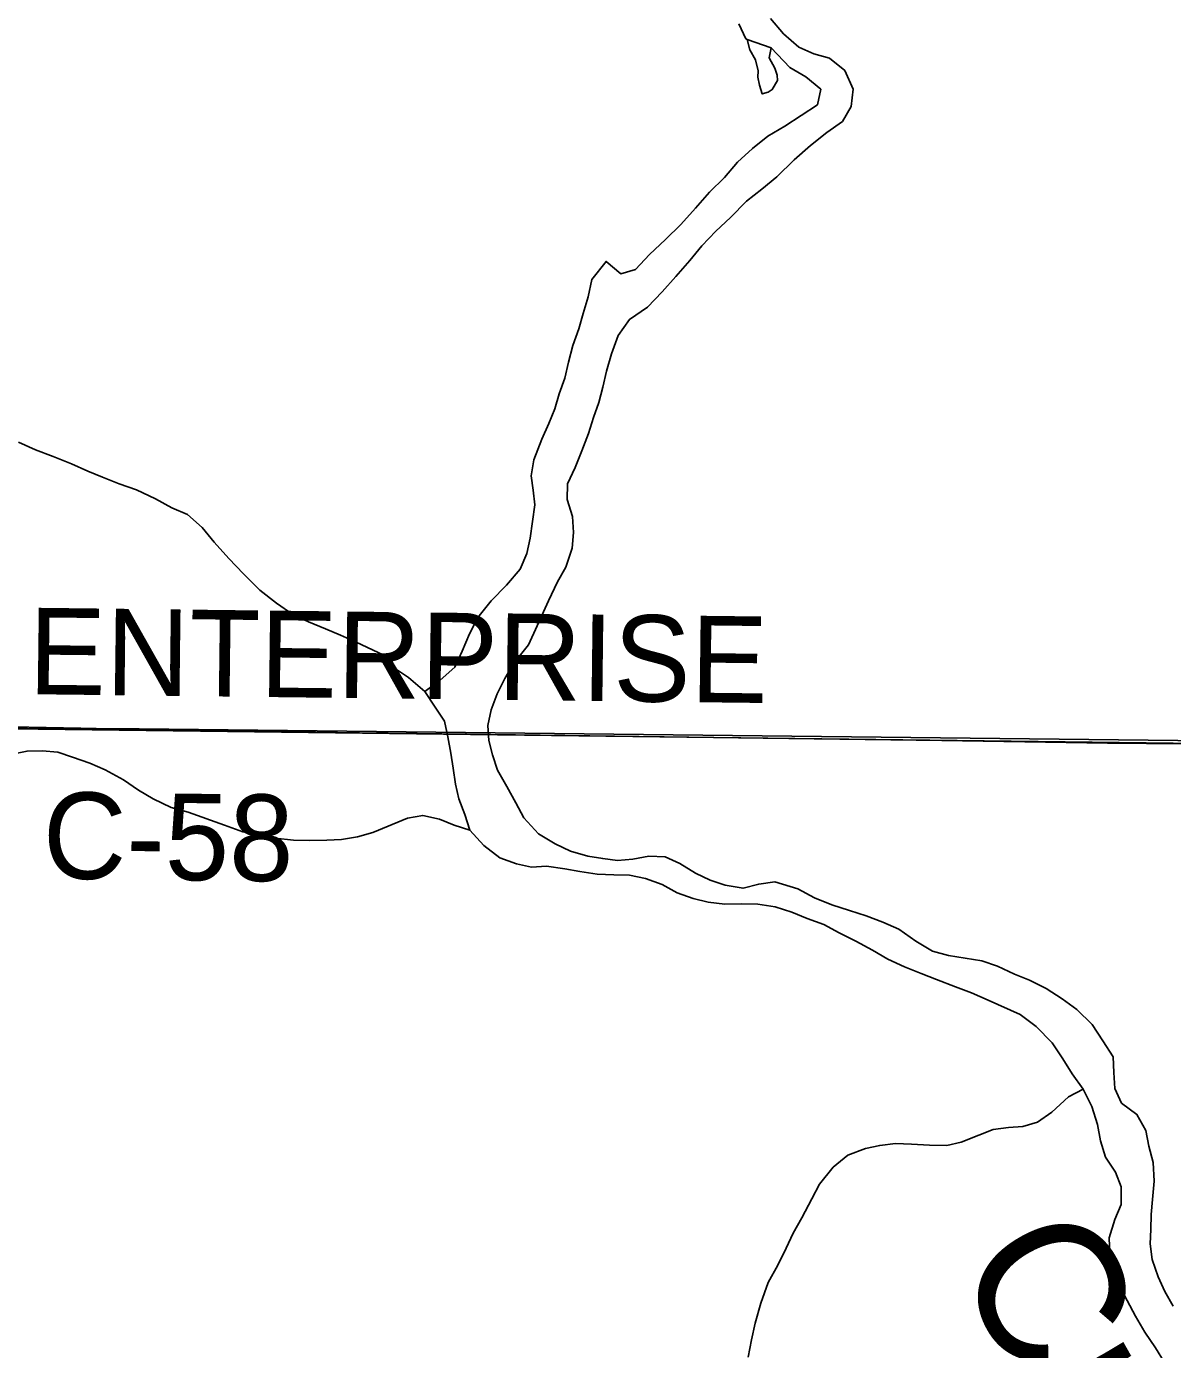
# Model space of a CAD drawing. Extents: x 0 to 34, y 0 to 22.
# Drawn here: x 7.507 to 8.26, y 17.907 to 18.776 of the extents above; entities that cross this region are included whole.
import ezdxf

# ---------------------------------------------------------------- set-up
doc = ezdxf.new("R2010")
doc.units = 0
for name, color, linetype in [('GM_X_Corporation', 7, 'Continuous'), ('GM_X_County_Road', 7, 'Continuous'), ('GM_X_County_Road_Text', 7, 'Continuous'), ('GM_X_Major_River', 7, 'Continuous'), ('GM_X_Major_River_Text', 7, 'Continuous'), ('GM_X_Minor_River', 7, 'Continuous')]:
    doc.layers.add(name, color=color, linetype=linetype)

msp = doc.modelspace()

# ---------------------------------------------------------------- linework, layer by layer
at = {"layer": 'GM_X_Corporation'}
for points in [[(8.49605, 19.31157), (8.49105, 18.30258), (7.47882, 18.31519), (7.49347, 19.32059)], [(8.49105, 18.30258), (8.48901, 17.21889), (7.47417, 17.23266), (7.47882, 18.31519)]]:
    msp.add_lwpolyline(points, close=True, dxfattribs=at)
for points in [[(8.49711, 18.30455), (7.58097, 18.31487), (7.55261, 18.31519), (7.54255, 18.31539), (7.37173, 18.31874)], [(7.37173, 18.31874), (7.54255, 18.31539), (7.55261, 18.31519), (7.58097, 18.31487), (8.49711, 18.30455)]]:
    msp.add_lwpolyline(points, dxfattribs=at)
at = {"layer": 'GM_X_County_Road'}
for points in [[(7.48288, 18.31538), (7.58147, 18.31452), (7.72562, 18.3124), (7.76351, 18.31188)], [(7.76351, 18.31188), (7.84429, 18.31078), (7.99087, 18.3088), (8.10832, 18.30725), (8.21705, 18.3055), (8.37111, 18.30423), (8.45811, 18.30343), (8.49736, 18.30357)]]:
    msp.add_lwpolyline(points, dxfattribs=at)
at = {"layer": 'GM_X_Major_River'}
msp.add_line((7.99614, 18.76228), (7.98031, 18.76789), dxfattribs=at)
for points in [[(7.81, 18.31713), (7.81208, 18.32733), (7.81607, 18.33787), (7.82119, 18.34802), (7.82707, 18.35815), (7.83677, 18.3701), (7.84231, 18.38251), (7.84983, 18.39906), (7.85575, 18.41146), (7.86124, 18.42122), (7.86526, 18.43366), (7.86621, 18.44388), (7.86564, 18.4545), (7.86205, 18.46557), (7.86224, 18.4758), (7.86738, 18.4867), (7.87175, 18.49762), (7.87613, 18.50891), (7.87936, 18.51947), (7.88296, 18.52927), (7.88542, 18.53946), (7.88789, 18.55003), (7.89114, 18.56135), (7.89553, 18.5734), (7.90293, 18.58388), (7.91484, 18.592), (7.92451, 18.60206), (7.93343, 18.61213), (7.94273, 18.62258), (7.95049, 18.6323), (7.95978, 18.64198), (7.96943, 18.65091), (7.97987, 18.66171), (7.98988, 18.66949), (7.99989, 18.67765), (8.0111, 18.68882), (8.02189, 18.6981), (8.03268, 18.70662), (8.04306, 18.71401), (8.04855, 18.72377), (8.0499, 18.73512), (8.04443, 18.74736), (8.03434, 18.75551), (8.02414, 18.75835), (8.01436, 18.76271), (8.00428, 18.77162), (7.99574, 18.78163)], [(7.97481, 18.77823), (7.97956, 18.76828), (7.98031, 18.76789)], [(7.98031, 18.76789), (7.98208, 18.76103), (7.98575, 18.75451), (7.98752, 18.74727), (7.98744, 18.7431), (7.98848, 18.73778), (7.99027, 18.73206), (7.99408, 18.73312), (7.99677, 18.73497), (8.0003, 18.74097), (7.99998, 18.74439)], [(7.99614, 18.76228), (8.00843, 18.74954), (8.01893, 18.74328), (8.02865, 18.73514), (8.02657, 18.72494), (8.00506, 18.71092), (7.99393, 18.7043), (7.98392, 18.69615), (7.97389, 18.68723), (7.96536, 18.67715), (7.95569, 18.66747), (7.94639, 18.65702), (7.93671, 18.6462), (7.92667, 18.63653), (7.91624, 18.62648), (7.90695, 18.6168), (7.89742, 18.61394), (7.8877, 18.62208), (7.87837, 18.61012), (7.87589, 18.59879), (7.87265, 18.58785), (7.86981, 18.57767), (7.86581, 18.56674), (7.86296, 18.5558), (7.86048, 18.54523), (7.85688, 18.53506), (7.85405, 18.52525), (7.85007, 18.51546), (7.84533, 18.50531), (7.84015, 18.49176), (7.83844, 18.48117), (7.83978, 18.47167), (7.84074, 18.46217), (7.8394, 18.4512), (7.83768, 18.44023), (7.8356, 18.43003), (7.83124, 18.41988), (7.82232, 18.40942), (7.81226, 18.39899), (7.80334, 18.38816), (7.79782, 18.37727), (7.79306, 18.36598), (7.78832, 18.35545), (7.77867, 18.34691), (7.76867, 18.33951), (7.77495, 18.32991), (7.78159, 18.31993), (7.78368, 18.30965), (7.78576, 18.299), (7.7871, 18.28912), (7.7888, 18.27847), (7.7909, 18.26895), (7.79488, 18.25864), (7.79811, 18.24834), (7.80741, 18.23831), (7.81788, 18.23015), (7.82881, 18.22616), (7.83864, 18.22408), (7.84851, 18.22466), (7.86062, 18.22292), (7.87046, 18.22122), (7.88181, 18.21949), (7.8928, 18.21891), (7.90304, 18.21872), (7.91363, 18.21663), (7.92456, 18.21264), (7.93432, 18.20715), (7.94488, 18.20354), (7.9547, 18.20108), (7.96568, 18.19974), (7.9763, 18.19992), (7.9873, 18.19972), (7.99865, 18.198), (8.00959, 18.19438), (8.01976, 18.1904), (8.03069, 18.18641), (8.04083, 18.18091), (8.05174, 18.1754), (8.06263, 18.16951), (8.07277, 18.16364), (8.08368, 18.15851), (8.0946, 18.15413), (8.10477, 18.15016), (8.1172, 18.14538), (8.12775, 18.14139), (8.13867, 18.13664), (8.15974, 18.12715), (8.17022, 18.11937), (8.18065, 18.10856), (8.18767, 18.09819), (8.19393, 18.08822), (8.20096, 18.07823), (8.20682, 18.06675), (8.21039, 18.05493), (8.21247, 18.04427), (8.21569, 18.0336), (8.22234, 18.02362), (8.22596, 18.01407), (8.22612, 18.00231), (8.22177, 17.99254), (8.21813, 17.98047)], [(7.99998, 18.74439), (7.99855, 18.74897), (7.99488, 18.75586), (7.99614, 18.76228)], [(8.26018, 17.93571), (8.25467, 17.94529), (8.25029, 17.95485), (8.24632, 17.9663), (8.245, 17.97656), (8.24555, 17.98603), (8.24573, 17.99588), (8.24667, 18.00573), (8.24765, 18.01784), (8.24712, 18.02998), (8.24428, 18.04065), (8.24219, 18.05093), (8.23632, 18.06165), (8.22621, 18.06905), (8.22183, 18.07861), (8.22127, 18.08923), (8.2207, 18.09948), (8.21406, 18.10984), (8.20705, 18.12059), (8.19699, 18.13063), (8.18725, 18.13764), (8.17675, 18.14427), (8.16585, 18.14978), (8.15606, 18.15376), (8.14477, 18.1589), (8.13459, 18.1625), (8.11265, 18.16594), (8.10208, 18.16878), (8.0912, 18.17543), (8.07996, 18.18322), (8.06942, 18.18797), (8.05849, 18.19196), (8.04755, 18.19557), (8.03586, 18.1992), (8.02456, 18.20396), (8.01367, 18.20985), (7.99857, 18.2143), (7.98793, 18.21298), (7.97763, 18.21014), (7.96591, 18.21225), (7.9561, 18.21547), (7.94632, 18.2202), (7.93619, 18.22645), (7.92641, 18.2308), (7.9158, 18.23138), (7.90513, 18.2293), (7.89525, 18.22834), (7.88541, 18.22966), (7.87557, 18.23136), (7.86425, 18.2346), (7.8541, 18.23934), (7.84321, 18.24599), (7.83354, 18.25641), (7.82841, 18.26636), (7.82254, 18.27709), (7.81629, 18.28782), (7.81306, 18.29774), (7.81057, 18.30726), (7.81, 18.31713)], [(8.21813, 17.98047), (8.21869, 17.96984), (8.22117, 17.96032), (8.2244, 17.95002), (8.22989, 17.9393), (8.23539, 17.92896), (8.24165, 17.91861), (8.24867, 17.90824), (8.25457, 17.89866), (8.2616, 17.88905)]]:
    msp.add_lwpolyline(points, dxfattribs=at)
at = {"layer": 'GM_X_Minor_River'}
for points in [[(7.50154, 18.50333), (7.51283, 18.49819), (7.52451, 18.4938), (7.53656, 18.48903), (7.5471, 18.48428), (7.55689, 18.48031), (7.56781, 18.47594), (7.57912, 18.47194), (7.59153, 18.46602), (7.60243, 18.46013), (7.61259, 18.45577), (7.6223, 18.44725), (7.63009, 18.43763), (7.63976, 18.42683), (7.64944, 18.41679), (7.66024, 18.40597), (7.67109, 18.39743), (7.68196, 18.39003), (7.69211, 18.38529), (7.70341, 18.38053), (7.7132, 18.37656), (7.72298, 18.3722), (7.73464, 18.36668), (7.74442, 18.36195), (7.74939, 18.35431), (7.7579, 18.34864), (7.76867, 18.33951)], [(7.79811, 18.24834), (7.78792, 18.25156), (7.77813, 18.25553), (7.76717, 18.25801), (7.75728, 18.2563), (7.73434, 18.24686), (7.72442, 18.24402), (7.71376, 18.24231), (7.70427, 18.24173), (7.6925, 18.24157), (7.68226, 18.24176), (7.67015, 18.24312), (7.65993, 18.24483), (7.64898, 18.24731), (7.63692, 18.2517), (7.61317, 18.2601), (7.60184, 18.26334), (7.59018, 18.26887), (7.58043, 18.27473), (7.57068, 18.28136), (7.55867, 18.28803), (7.5485, 18.29239), (7.53719, 18.29639), (7.52739, 18.29961), (7.51716, 18.30055), (7.50729, 18.30035), (7.49739, 18.29826)], [(8.20096, 18.07823), (8.19138, 18.0731), (8.18057, 18.06306), (8.17096, 18.05642), (8.16142, 18.05356), (8.15193, 18.05298), (8.14204, 18.05164), (8.13249, 18.04802), (8.12102, 18.04331), (8.11149, 18.04121), (8.10011, 18.04142), (8.08836, 18.04202), (8.07775, 18.04259), (8.06748, 18.04126), (8.05796, 18.03916), (8.04649, 18.03483), (8.03686, 18.02704), (8.02793, 18.01583), (8.02282, 18.00607), (8.01614, 17.99368), (8.01064, 17.98354), (8.00591, 17.97377), (8.00039, 17.9625), (7.99411, 17.95124), (7.98931, 17.93768), (7.98565, 17.92448), (7.98317, 17.91353), (7.98107, 17.90219)]]:
    msp.add_lwpolyline(points, dxfattribs=at)

# ---------------------------------------------------------------- texts
at = {"layer": 'GM_X_County_Road_Text'}
for s, rotation, p in [('ENTERPRISE', 359.31121, (7.50806, 18.33771)), ('C-58', 359.32214, (7.51736, 18.21664))]:
    msp.add_text(s, height=0.056818, rotation=rotation, dxfattribs=at).set_placement(p)
at = {"layer": 'GM_X_Major_River_Text'}
msp.add_text('Creek', height=0.094667, rotation=299.4619, dxfattribs=at).set_placement((8.11505, 17.96329))

doc.saveas('drawing.dxf')
